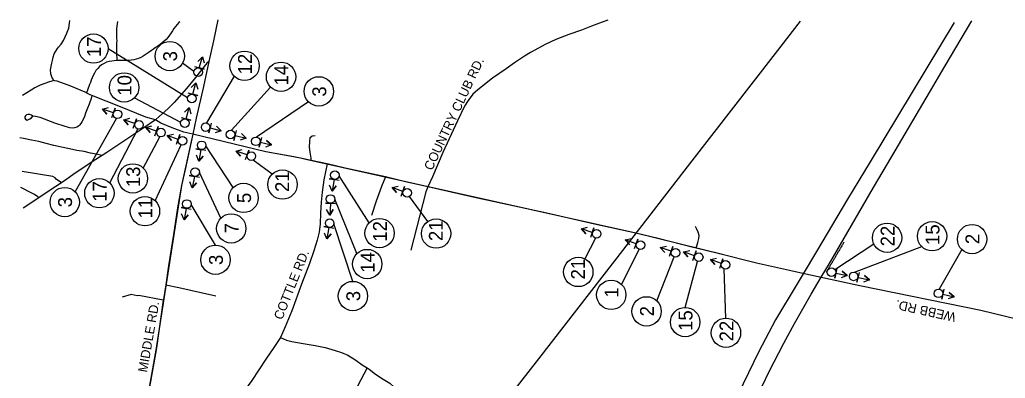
# Model space of a CAD drawing. Extents: x 1123038 to 1172987, y 554419 to 623636.
# Drawn here: x 1123091 to 1134979, y 574867 to 579193 of the extents above; entities that cross this region are included whole.
import ezdxf

# ---------------------------------------------------------------- set-up
doc = ezdxf.new("R2010")
doc.units = 0
for name, color, linetype in [('CENTERLINE', 7, 'Continuous'), ('D_Text_Standard', 7, 'Continuous'), ('Default', 7, 'Continuous'), ('Maine_E911_Roads', 7, 'Continuous'), ('Metwp24L', 7, 'Continuous'), ('S_Guardrail_Beam', 7, 'Continuous')]:
    doc.layers.add(name, color=color, linetype=linetype)

msp = doc.modelspace()

# ---------------------------------------------------------------- linework, layer by layer
at = {"layer": 'CENTERLINE'}
for points in [[(1125179, 577813), (1125085, 577387), (1125042, 577195), (1124733, 575208), (1124438, 573567)], [(1131569, 576360), (1130523, 576618), (1126542, 577508), (1126477, 577523), (1126349, 577548), (1126061, 577599), (1125179, 577813)]]:
    msp.add_lwpolyline(points, dxfattribs=at)
at = {"layer": 'D_Text_Standard'}
for p, q in [((1124158, 578845), (1125115, 578255)), ((1125192, 578570), (1125054, 578667)), ((1125678, 578512), (1125344, 577949)), ((1126118, 578380), (1125645, 577860)), ((1124476, 578251), (1125032, 577957)), ((1126574, 578204), (1125949, 577777)), ((1123759, 577118), (1124257, 578003)), ((1124177, 577225), (1124515, 577874)), ((1124581, 577404), (1124780, 577781)), ((1124727, 577008), (1125040, 577683)), ((1125667, 577169), (1125338, 577671)), ((1126136, 577330), (1125909, 577500)), ((1125518, 576800), (1125258, 577349)), ((1127307, 576744), (1126944, 577310)), ((1127790, 577059), (1128010, 576759)), ((1125453, 576474), (1125158, 576963)), ((1127158, 576371), (1126893, 577030)), ((1127110, 576037), (1126881, 576732)), ((1130035, 576559), (1129907, 576308)), ((1132925, 576178), (1133393, 576491)), ((1133159, 576148), (1133971, 576456)), ((1130351, 576000), (1130564, 576423)), ((1130777, 575800), (1130986, 576332)), ((1134453, 576421), (1134182, 575943)), ((1131118, 575722), (1131266, 576278)), ((1131610, 575594), (1131590, 576186))]:
    msp.add_line(p, q, dxfattribs=at)
for centre in [(1123981, 578845), (1124901, 578754), (1125803, 578637), (1126243, 578505), (1124351, 578376), (1126699, 578329), (1124456, 577279), (1124052, 577100), (1126261, 577205), (1123634, 576993), (1125792, 577044), (1124602, 576883), (1125643, 576675), (1127432, 576619), (1128114, 576613), (1133553, 576563), (1134096, 576581), (1134578, 576546), (1125453, 576297), (1127283, 576246), (1129829, 576150), (1127110, 575860), (1130226, 575874), (1130652, 575675), (1131118, 575545), (1131610, 575417)]:
    msp.add_circle(centre, 177, dxfattribs=at)
at = {"layer": 'Default'}
for points in [[(1125198, 578627), (1125316, 578595), (1125257, 578611), (1125294, 578746), (1125238, 578689), (1125294, 578746), (1125317, 578672)], [(1125120, 578312), (1125238, 578280), (1125179, 578296), (1125217, 578431), (1125160, 578374), (1125217, 578431), (1125240, 578357)], [(1124201, 578012), (1124241, 578127), (1124221, 578069), (1124089, 578115), (1124142, 578055), (1124089, 578115), (1124164, 578134)], [(1125038, 578014), (1125155, 577982), (1125097, 577998), (1125134, 578133), (1125077, 578076), (1125134, 578133), (1125157, 578059)], [(1124458, 577883), (1124498, 577999), (1124478, 577941), (1124346, 577987), (1124399, 577927), (1124346, 577987), (1124421, 578005)], [(1124723, 577791), (1124763, 577906), (1124743, 577848), (1124611, 577894), (1124664, 577834), (1124611, 577894), (1124686, 577913)], [(1125401, 577946), (1125373, 577827), (1125387, 577887), (1125523, 577854), (1125464, 577909), (1125523, 577854), (1125450, 577828)], [(1124983, 577692), (1125023, 577808), (1125003, 577750), (1124871, 577796), (1124924, 577736), (1124871, 577796), (1124946, 577814)], [(1125702, 577857), (1125674, 577738), (1125688, 577798), (1125824, 577765), (1125765, 577820), (1125824, 577765), (1125751, 577739)], [(1126006, 577774), (1125978, 577655), (1125992, 577714), (1126128, 577682), (1126069, 577736), (1126128, 577682), (1126055, 577656)], [(1125338, 577614), (1125217, 577635), (1125277, 577625), (1125253, 577487), (1125304, 577549), (1125253, 577487), (1125223, 577558)], [(1125813, 577505), (1125853, 577620), (1125833, 577563), (1125701, 577609), (1125754, 577549), (1125701, 577609), (1125776, 577627)], [(1125258, 577291), (1125137, 577313), (1125198, 577302), (1125173, 577165), (1125224, 577226), (1125173, 577165), (1125143, 577236)], [(1126944, 577253), (1126824, 577275), (1126884, 577264), (1126859, 577126), (1126910, 577188), (1126859, 577126), (1126829, 577197)], [(1127693, 577064), (1127734, 577180), (1127714, 577122), (1127582, 577168), (1127635, 577108), (1127582, 577168), (1127656, 577186)], [(1125158, 576905), (1125038, 576927), (1125098, 576916), (1125073, 576779), (1125124, 576840), (1125073, 576779), (1125043, 576850)], [(1126900, 576973), (1126778, 576979), (1126839, 576976), (1126831, 576837), (1126874, 576904), (1126831, 576837), (1126793, 576903)], [(1126881, 576675), (1126761, 576697), (1126821, 576686), (1126796, 576548), (1126847, 576610), (1126796, 576548), (1126767, 576619)], [(1129978, 576568), (1130018, 576683), (1129998, 576626), (1129866, 576672), (1129919, 576612), (1129866, 576672), (1129941, 576690)], [(1130508, 576432), (1130548, 576547), (1130528, 576490), (1130396, 576536), (1130449, 576476), (1130396, 576536), (1130471, 576554)], [(1130930, 576341), (1130970, 576457), (1130950, 576399), (1130818, 576445), (1130871, 576385), (1130818, 576445), (1130893, 576463)], [(1131210, 576287), (1131250, 576403), (1131230, 576345), (1131098, 576391), (1131151, 576331), (1131098, 576391), (1131173, 576409)], [(1131534, 576195), (1131574, 576310), (1131554, 576253), (1131422, 576299), (1131475, 576239), (1131422, 576299), (1131497, 576317)], [(1132949, 576196), (1132922, 576077), (1132936, 576137), (1133072, 576106), (1133012, 576160), (1133072, 576106), (1133000, 576079)], [(1133217, 576145), (1133190, 576026), (1133203, 576085), (1133340, 576054), (1133280, 576108), (1133340, 576054), (1133267, 576028)], [(1134239, 575941), (1134212, 575821), (1134226, 575881), (1134362, 575850), (1134302, 575904), (1134362, 575850), (1134290, 575824)]]:
    msp.add_lwpolyline(points, dxfattribs=at)
for centre in [(1125243, 578559), (1125166, 578244), (1124272, 578052), (1125083, 577946), (1124530, 577924), (1124795, 577831), (1125334, 577898), (1125054, 577733), (1125635, 577809), (1125939, 577726), (1125286, 577678), (1125885, 577546), (1125206, 577355), (1126893, 577317), (1127765, 577105), (1126841, 577030), (1125106, 576970), (1126830, 576739), (1130050, 576609), (1130579, 576473), (1131001, 576382), (1131281, 576328), (1131605, 576236), (1132883, 576148), (1133150, 576097), (1134173, 575892)]:
    msp.add_circle(centre, 51.9, dxfattribs=at)
at = {"layer": 'Maine_E911_Roads'}
for points in [[(1123501, 578459), (1123494, 578474), (1123484, 578493), (1123466, 578539), (1123464, 578588), (1123477, 578669), (1123485, 578703), (1123494, 578741), (1123507, 578783), (1123547, 578846), (1123559, 578861), (1123590, 578900), (1123619, 578944), (1123660, 579031), (1123663, 579041), (1123685, 579092), (1123692, 579150), (1123694, 579184)], [(1124271, 579171), (1124265, 579143), (1124263, 579114), (1124258, 579086), (1124259, 579056), (1124259, 579027), (1124260, 578997), (1124260, 578969), (1124261, 578940), (1124259, 578913), (1124260, 578885), (1124260, 578859), (1124259, 578836), (1124259, 578813), (1124260, 578792), (1124260, 578772), (1124260, 578756), (1124261, 578741), (1124261, 578700)], [(1125482, 579193), (1125429, 578940), (1125374, 578688)], [(1130185, 579189), (1130116, 579163), (1129989, 579115), (1129867, 579067), (1129715, 579015), (1129557, 578953), (1129431, 578894), (1129347, 578850), (1129251, 578797), (1129181, 578755), (1129059, 578674), (1128957, 578602), (1128795, 578487), (1128615, 578348), (1128558, 578296), (1128499, 578220), (1128456, 578152), (1128372, 577973), (1128196, 577593), (1128071, 577297), (1128013, 577178)], [(1131810, 574255), (1131981, 574632), (1132046, 574774), (1132130, 574949), (1132308, 575290), (1132437, 575529), (1132637, 575882), (1132759, 576087), (1132857, 576253), (1133391, 577168), (1133611, 577543), (1134066, 578317), (1134254, 578635), (1134576, 579178)], [(1125021, 579169), (1125010, 579159), (1124989, 579137), (1124972, 579112), (1124952, 579086), (1124935, 579059), (1124917, 579033), (1124898, 579006), (1124879, 578980), (1124858, 578956), (1124835, 578933), (1124811, 578913), (1124785, 578893), (1124757, 578874), (1124731, 578856), (1124705, 578837), (1124679, 578820), (1124654, 578802), (1124629, 578785), (1124605, 578768), (1124579, 578753), (1124553, 578738), (1124525, 578726), (1124497, 578717), (1124466, 578710), (1124437, 578705), (1124406, 578701), (1124375, 578700), (1124345, 578700), (1124315, 578701), (1124288, 578700), (1124261, 578700)], [(1134361, 579160), (1133350, 577479), (1133077, 577028), (1132700, 576397), (1132542, 576128), (1132469, 576007), (1132208, 575573), (1132008, 575192), (1131818, 574801), (1131614, 574338)], [(1124261, 578700), (1124232, 578698), (1124202, 578694), (1124171, 578689), (1124139, 578680), (1124108, 578666), (1124078, 578649), (1124054, 578628), (1124032, 578604), (1124011, 578579), (1123993, 578549), (1123979, 578520), (1123966, 578492), (1123955, 578465), (1123944, 578437), (1123935, 578411), (1123925, 578386), (1123917, 578368), (1123914, 578354), (1123897, 578310)], [(1125374, 578688), (1125348, 578667), (1125270, 578571), (1125194, 578476), (1125104, 578365), (1124954, 578195), (1124878, 578118), (1124775, 578024), (1124728, 577984)], [(1125374, 578688), (1125309, 578386), (1125220, 578007), (1125179, 577813)], [(1123501, 578459), (1123479, 578451), (1123440, 578438), (1123393, 578423), (1123336, 578402), (1123272, 578370), (1123228, 578343), (1123124, 578280)], [(1123897, 578310), (1123882, 578318), (1123709, 578390), (1123543, 578453), (1123515, 578456), (1123501, 578459)], [(1123960, 578278), (1123952, 578242), (1123929, 578176), (1123910, 578128), (1123886, 578065), (1123872, 578025), (1123856, 577991), (1123842, 577963), (1123829, 577943), (1123813, 577923), (1123799, 577908), (1123779, 577896), (1123753, 577887), (1123725, 577885), (1123697, 577890), (1123640, 577905), (1123516, 577947), (1123337, 578012), (1123280, 578027), (1123248, 578030), (1123235, 578043), (1123215, 578049), (1123192, 578050), (1123173, 578045), (1123160, 578035), (1123153, 578022), (1123154, 578005), (1123162, 577992), (1123180, 577983), (1123197, 577988), (1123215, 577998), (1123234, 578011), (1123248, 578030)], [(1123960, 578278), (1123940, 578286), (1123900, 578308), (1123897, 578310)], [(1124728, 577984), (1124613, 578018), (1124305, 578141), (1123960, 578278)], [(1124728, 577984), (1124588, 577890), (1124337, 577721), (1124142, 577592), (1124085, 577555)], [(1125179, 577813), (1125072, 577837), (1124932, 577889), (1124794, 577946), (1124728, 577984)], [(1124085, 577555), (1124064, 577561), (1124013, 577573), (1123947, 577585), (1123868, 577602), (1123779, 577617), (1123690, 577635), (1123596, 577655), (1123504, 577676), (1123412, 577699), (1123321, 577722), (1123232, 577742), (1123138, 577759), (1123091, 577767)], [(1125179, 577813), (1125158, 577722), (1125042, 577195), (1124995, 576925), (1124947, 576601), (1124887, 576226), (1124855, 575995)], [(1126607, 577494), (1126477, 577523), (1126398, 577538), (1126061, 577599), (1125179, 577813)], [(1126607, 577494), (1126608, 577522), (1126603, 577546), (1126593, 577594), (1126587, 577654), (1126592, 577722), (1126596, 577774), (1126619, 577794), (1126655, 577798)], [(1124085, 577555), (1123978, 577486), (1123731, 577321), (1123658, 577270), (1123594, 577226)], [(1126800, 577453), (1126759, 577262), (1126738, 577114), (1126726, 576994), (1126721, 576861), (1126714, 576731), (1126704, 576629), (1126681, 576535), (1126640, 576405), (1126586, 576254), (1126491, 576002), (1126374, 575681), (1126293, 575488), (1126236, 575360)], [(1126800, 577453), (1126607, 577494)], [(1127504, 577296), (1127447, 577308), (1127016, 577404), (1126800, 577453)], [(1123594, 577226), (1123530, 577271), (1123517, 577286), (1123492, 577302), (1123119, 577364)], [(1127504, 577296), (1127455, 577181), (1127389, 577005), (1127334, 576831)], [(1128013, 577178), (1127761, 577234), (1127504, 577296)], [(1123323, 577045), (1123308, 577057), (1123271, 577085), (1123190, 577123), (1123152, 577145), (1123105, 577171)], [(1123594, 577226), (1123459, 577136), (1123323, 577045)], [(1128013, 577178), (1127991, 577118), (1127809, 576413)], [(1130523, 576618), (1130023, 576726), (1129448, 576860), (1128578, 577049), (1128013, 577178)], [(1123323, 577045), (1123308, 577036), (1123134, 576920)], [(1131252, 576438), (1131272, 576507), (1131284, 576555), (1131285, 576588), (1131273, 576630), (1131256, 576673), (1131244, 576697)], [(1131252, 576438), (1131216, 576445), (1130792, 576552), (1130523, 576618)], [(1135357, 575524), (1135278, 575539), (1134683, 575685), (1133226, 575982), (1132575, 576122), (1132376, 576166), (1131980, 576258), (1131516, 576373), (1131252, 576438)], [(1124855, 575995), (1124824, 575818), (1124822, 575809)], [(1124855, 575995), (1125010, 575962), (1125455, 575863)], [(1124822, 575809), (1124527, 575868), (1124506, 575863), (1124434, 575877), (1124329, 575845)], [(1124822, 575809), (1124740, 575234), (1124668, 574827), (1124576, 574348), (1124517, 574035), (1124471, 573763), (1124438, 573567)], [(1126236, 575360), (1126156, 575239), (1126058, 575098), (1125890, 574841), (1125746, 574645), (1125527, 574323), (1125226, 573875), (1125024, 573582), (1124965, 573483)], [(1126236, 575360), (1126309, 575329), (1126373, 575312), (1126510, 575286), (1126655, 575261), (1126775, 575237), (1126895, 575203), (1126973, 575179), (1127047, 575148), (1127134, 575095), (1127235, 575023), (1127283, 574992)], [(1127283, 574992), (1127165, 574774), (1127137, 574585), (1127102, 574413), (1127059, 574276), (1127060, 574217), (1127087, 574162), (1127122, 574131), (1127157, 574112), (1127255, 574097), (1127398, 574075), (1127550, 574060)], [(1127283, 574992), (1127305, 574978), (1127384, 574919), (1127477, 574858), (1127554, 574807), (1127609, 574762), (1127660, 574698), (1127666, 574633), (1127649, 574526), (1127623, 574392), (1127597, 574287), (1127568, 574134), (1127550, 574060)]]:
    msp.add_lwpolyline(points, dxfattribs=at)
at = {"layer": 'Metwp24L'}
msp.add_lwpolyline([(1132505, 579176), (1132202, 578786), (1131172, 577456), (1130264, 576283), (1129347, 575104), (1128489, 574000), (1127306, 572480), (1126860, 571905)], dxfattribs=at)
at = {"layer": 'S_Guardrail_Beam'}
msp.add_lwpolyline([(1133034, 576511), (1133029, 576502), (1133024, 576494), (1133019, 576485), (1133014, 576476), (1133011, 576472), (1133006, 576464), (1133001, 576455), (1132996, 576446), (1132991, 576438), (1132988, 576433), (1132983, 576425), (1132978, 576416), (1132973, 576407), (1132971, 576404), (1132966, 576395), (1132961, 576387), (1132956, 576378), (1132951, 576369), (1132946, 576361), (1132941, 576352), (1132936, 576344), (1132931, 576335), (1132926, 576326), (1132923, 576321), (1132918, 576313), (1132916, 576309), (1132911, 576301), (1132906, 576293), (1132901, 576284), (1132896, 576276), (1132896, 576275), (1132891, 576267), (1132886, 576258), (1132881, 576251), (1132877, 576245), (1132872, 576236), (1132867, 576227), (1132862, 576219), (1132857, 576210), (1132856, 576209), (1132851, 576200), (1132846, 576191), (1132841, 576183), (1132836, 576174), (1132832, 576167), (1132827, 576159), (1132822, 576150), (1132819, 576146)], dxfattribs=at)
msp.add_lwpolyline([(1133034, 576511), (1133029, 576502), (1133024, 576494), (1133019, 576485), (1133014, 576476), (1133011, 576472), (1133006, 576464), (1133001, 576455), (1132996, 576446), (1132991, 576438), (1132988, 576433), (1132983, 576425), (1132978, 576416), (1132973, 576407), (1132971, 576404), (1132966, 576395), (1132961, 576387), (1132956, 576378), (1132951, 576369), (1132946, 576361), (1132941, 576352), (1132936, 576344), (1132931, 576335), (1132926, 576326), (1132923, 576321), (1132918, 576313), (1132916, 576309), (1132911, 576301), (1132906, 576293), (1132901, 576284), (1132896, 576276), (1132896, 576275), (1132891, 576267), (1132886, 576258), (1132881, 576251), (1132877, 576245), (1132872, 576236), (1132867, 576227), (1132862, 576219), (1132857, 576210), (1132856, 576209), (1132851, 576200), (1132846, 576191), (1132841, 576183), (1132836, 576174), (1132832, 576167), (1132827, 576159), (1132822, 576150), (1132819, 576146)], dxfattribs=at)

# ---------------------------------------------------------------- texts
at = {"layer": 'D_Text_Standard'}
for s, height, rotation, p in [('17', 167.1, 90, (1124070, 578742)), ('3', 167, 90, (1124989, 578691)), ('12', 167.1, 90, (1125892, 578534)), ('COUNTRY CLUB RD.', 111.99, 64.7672, (1128064, 577366)), ('14', 167.1, 90, (1126331, 578399)), ('10', 167.1, 90, (1124439, 578277)), ('3', 167, 90, (1126788, 578265)), ('13', 167.1, 90, (1124544, 577173)), ('21', 167.1, 90, (1126341, 577115)), ('17', 167.1, 90, (1124140, 576997)), ('3', 167, 90, (1123722, 576930)), ('11', 167.1, 90, (1124690, 576795)), ('5', 167, 90, (1125881, 576981)), ('7', 167, 90, (1125731, 576615)), ('12', 167.1, 90, (1127520, 576516)), ('21', 167.1, 90, (1128194, 576523)), ('22', 167.1, 90, (1133643, 576459)), ('15', 167.1, 90, (1134185, 576476)), ('2', 167, 90, (1134666, 576486)), ('3', 167, 90, (1125542, 576234)), ('COTTLE RD.', 112, 68.2668, (1126256, 575564)), ('14', 167.1, 90, (1127371, 576141)), ('21', 167.1, 90, (1129909, 576060)), ('3', 167, 90, (1127198, 575797)), ('1', 167, 90, (1130313, 575841)), ('MIDDLE RD.', 112, 80.1471, (1124628, 574933)), ('2', 167, 90, (1130741, 575615)), ('WEBB RD.', 112, 167.4702, (1134391, 575654)), ('15', 167.1, 90, (1131206, 575439)), ('22', 167.1, 90, (1131700, 575313))]:
    msp.add_text(s, height=height, rotation=rotation, dxfattribs=at).set_placement(p)

doc.saveas('drawing.dxf')
